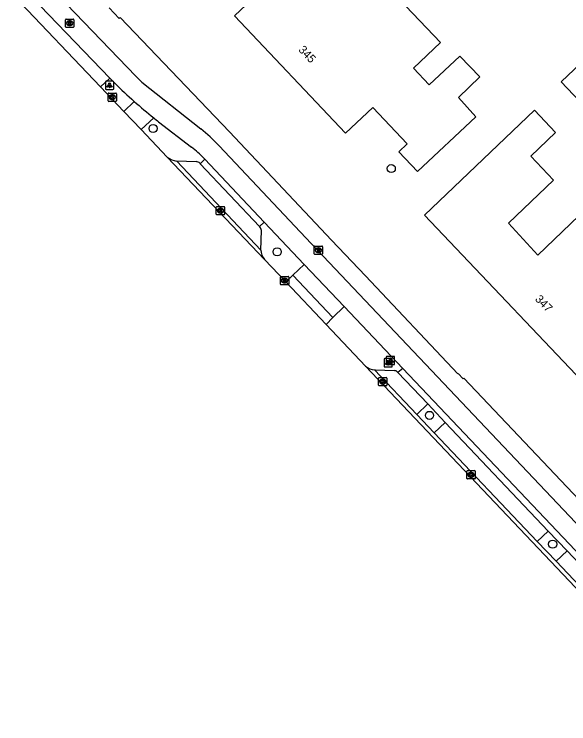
# Model space of a CAD drawing. Extents: x 162532 to 163264, y 381233 to 382042.
# Drawn here: x 163046.9 to 163113.5, y 381251.9 to 381337 of the extents above; entities that cross this region are included whole.
import ezdxf

# ---------------------------------------------------------------- set-up
doc = ezdxf.new("R2010")
doc.units = 0
for name, color, linetype in [('IMGEO_Berm_open', 7, 'Continuous'), ('IMGEO_Boom', 7, 'Continuous'), ('IMGEO_Brandkraan', 7, 'Continuous'), ('IMGEO_Fietspad_gesloten', 7, 'Continuous'), ('IMGEO_Kolk', 7, 'Continuous'), ('IMGEO_Lichtpunt', 7, 'Continuous'), ('IMGEO_Pand', 7, 'Continuous'), ('IMGEO_Pand_nummerreeks', 7, 'Continuous'), ('IMGEO_Parkeervlak_open', 7, 'Continuous'), ('IMGEO_Rijbaan_lokaal_gesloten', 7, 'Continuous'), ('IMGEO_Rijbaan_lokaal_open', 7, 'Continuous'), ('IMGEO_Rioolput', 7, 'Continuous'), ('IMGEO_Voetpad_open', 7, 'Continuous')]:
    doc.layers.add(name, color=color, linetype=linetype)

msp = doc.modelspace()

# ---------------------------------------------------------------- linework, layer by layer
at = {"layer": 'IMGEO_Berm_open'}
for points in [[(163069.769, 381319.62), (163069.229, 381319.072)], [(163076.341, 381311.55), (163076.898, 381312.067)], [(163093.518, 381294.532), (163092.951, 381294.025)], [(163096.521, 381290.265), (163098.617, 381288.057)], [(163113.256, 381272.637), (163110.99, 381275.023)]]:
    msp.add_lwpolyline(points, dxfattribs=at)
at = {"layer": 'IMGEO_Boom'}
for centre in [(163063.565, 381323.301), (163092.143, 381318.497), (163078.459, 381308.505), (163096.733, 381288.889), (163111.511, 381273.445)]:
    msp.add_circle(centre, 0.489, dxfattribs=at)
at = {"layer": 'IMGEO_Brandkraan'}
for p, q in [((163082.901, 381308.266), (163082.901, 381309.118)), ((163082.976, 381309.192), (163083.828, 381309.192)), ((163083.389, 381308.972), (163083.414, 381308.972)), ((163083.902, 381309.118), (163083.902, 381308.266)), ((163083.828, 381308.192), (163082.976, 381308.192)), ((163083.412, 381308.412), (163083.387, 381308.412))]:
    msp.add_line(p, q, dxfattribs=at)
for points in [[(163082.901, 381308.266), (163082.901, 381309.118)], [(163082.976, 381309.192), (163083.828, 381309.192)], [(163083.249, 381308.892), (163083.249, 381308.492), (163083.462, 381308.492)], [(163083.48, 381308.892), (163083.249, 381308.892)], [(163083.428, 381308.811), (163083.374, 381308.811), (163083.374, 381308.735)], [(163083.902, 381309.118), (163083.902, 381308.266)], [(163083.828, 381308.192), (163082.976, 381308.192)], [(163083.374, 381308.735), (163083.427, 381308.735)], [(163083.436, 381308.659), (163083.374, 381308.659), (163083.374, 381308.578)], [(163083.374, 381308.578), (163083.436, 381308.578)]]:
    msp.add_lwpolyline(points, dxfattribs=at)
for centre, radius, start, end in [((163082.978, 381309.116), 0.0765, 91.55205, 178.44795), ((163082.978, 381309.116), 0.0765, 91.55205, 178.44795), ((163083.429, 381308.773), 0.0379, 267.82845, 90.93552), ((163083.484, 381308.747), 0.145, 59.4692, 91.53667), ((163083.509, 381308.794), 0.0922, 285.51372, 58.15012), ((163083.826, 381309.116), 0.0765, 1.55205, 88.44795), ((163083.826, 381309.116), 0.0765, 1.55205, 88.44795), ((163082.978, 381308.268), 0.0765, 181.55205, 268.44795), ((163082.978, 381308.268), 0.0765, 181.55205, 268.44795), ((163083.437, 381308.618), 0.0404, 269.87594, 90.50774), ((163083.468, 381308.743), 0.251, 268.66757, 293.53466), ((163083.514, 381308.602), 0.105, 301.31148, 78.98903), ((163083.826, 381308.268), 0.0765, 271.55205, 358.44795), ((163083.826, 381308.268), 0.0765, 271.55205, 358.44795)]:
    msp.add_arc(centre, radius, start, end, dxfattribs=at)
for centre, major_axis, ratio, start_param, end_param in [((163083.388, 381308.692), (-0.387, 0.002), 0.722429, 4.712389, 7.853982), ((163083.413, 381308.692), (-0.39, 0.002), 0.717154, 1.570796, 4.712389)]:
    msp.add_ellipse(centre, major_axis=major_axis, ratio=ratio, start_param=start_param, end_param=end_param, dxfattribs=at)
at = {"layer": 'IMGEO_Fietspad_gesloten'}
for points in [[(163049.024, 381342.557), (163061.485, 381329.585), (163062.213, 381328.878), (163069.293, 381323.282)], [(163058.375, 381329.349), (163058.969, 381328.729)], [(163064.228, 381324.12), (163068.172, 381321.081)], [(163071.49, 381321.218), (163082.544, 381309.501), (163135.158, 381253.984), (163136.659, 381252.418)], [(163069.687, 381319.707), (163069.769, 381319.62)], [(163069.769, 381319.62), (163076.898, 381312.067)], [(163076.898, 381312.067), (163081.69, 381306.989)], [(163086.482, 381301.942), (163093.518, 381294.532)], [(163093.518, 381294.532), (163129.771, 381256.351)]]:
    msp.add_lwpolyline(points, dxfattribs=at)
for centre, radius, start, end in [((163102.92, 381373.565), 62.785, 225.57143, 228.47668), ((163102.439, 381373.008), 62.05, 228.46808, 231.30457), ((163102.873, 381373.527), 62.725, 231.29153, 231.96845), ((163055.156, 381306.033), 22.302, 42.91261, 50.66302), ((163058.539, 381308.937), 15.501, 44.01146, 51.57684)]:
    msp.add_arc(centre, radius, start, end, dxfattribs=at)
at = {"layer": 'IMGEO_Kolk'}
for p, q in [((163058.243, 381327.554), (163059.095, 381327.554)), ((163058.168, 381326.628), (163058.168, 381327.48)), ((163058.679, 381326.774), (163058.654, 381326.774)), ((163058.656, 381327.334), (163058.681, 381327.334)), ((163059.169, 381327.48), (163059.169, 381326.628)), ((163059.095, 381326.554), (163058.243, 381326.554)), ((163071.149, 381313.021), (163071.149, 381313.873)), ((163071.224, 381313.947), (163072.076, 381313.947)), ((163072.15, 381313.873), (163072.15, 381313.021)), ((163071.66, 381313.167), (163071.635, 381313.167)), ((163071.637, 381313.727), (163071.662, 381313.727)), ((163072.076, 381312.947), (163071.224, 381312.947)), ((163078.834, 381304.631), (163078.834, 381305.483)), ((163078.909, 381305.557), (163079.761, 381305.557)), ((163079.835, 381305.483), (163079.835, 381304.631)), ((163079.761, 381304.557), (163078.909, 381304.557)), ((163079.345, 381304.777), (163079.32, 381304.777)), ((163079.322, 381305.337), (163079.347, 381305.337)), ((163090.625, 381292.511), (163090.625, 381293.363)), ((163090.7, 381293.437), (163091.552, 381293.437)), ((163091.136, 381292.657), (163091.111, 381292.657)), ((163091.113, 381293.217), (163091.138, 381293.217)), ((163091.626, 381293.363), (163091.626, 381292.511)), ((163091.552, 381292.437), (163090.7, 381292.437)), ((163101.215, 381281.337), (163101.215, 381282.189)), ((163101.29, 381282.263), (163102.142, 381282.263)), ((163101.703, 381282.043), (163101.728, 381282.043)), ((163102.216, 381282.189), (163102.216, 381281.337)), ((163102.142, 381281.263), (163101.29, 381281.263)), ((163101.726, 381281.483), (163101.701, 381281.483))]:
    msp.add_line(p, q, dxfattribs=at)
for points in [[(163058.243, 381327.554), (163059.095, 381327.554)], [(163058.168, 381326.628), (163058.168, 381327.48)], [(163058.489, 381327.254), (163058.612, 381327.254), (163058.612, 381327.103), (163058.742, 381327.254), (163058.906, 381327.254), (163058.76, 381327.103), (163058.913, 381326.854), (163058.761, 381326.854), (163058.676, 381327.018), (163058.612, 381326.951), (163058.612, 381326.854), (163058.489, 381326.854), (163058.489, 381327.254)], [(163059.169, 381327.48), (163059.169, 381326.628)], [(163059.095, 381326.554), (163058.243, 381326.554)], [(163071.149, 381313.021), (163071.149, 381313.873)], [(163071.224, 381313.947), (163072.076, 381313.947)], [(163072.15, 381313.873), (163072.15, 381313.021)], [(163071.47, 381313.647), (163071.593, 381313.647), (163071.593, 381313.496), (163071.723, 381313.647), (163071.887, 381313.647), (163071.741, 381313.496), (163071.894, 381313.247), (163071.742, 381313.247), (163071.657, 381313.411), (163071.593, 381313.344), (163071.593, 381313.247), (163071.47, 381313.247), (163071.47, 381313.647)], [(163072.076, 381312.947), (163071.224, 381312.947)], [(163078.834, 381304.631), (163078.834, 381305.483)], [(163078.909, 381305.557), (163079.761, 381305.557)], [(163079.835, 381305.483), (163079.835, 381304.631)], [(163079.761, 381304.557), (163078.909, 381304.557)], [(163079.155, 381305.257), (163079.278, 381305.257), (163079.278, 381305.106), (163079.408, 381305.257), (163079.572, 381305.257), (163079.426, 381305.106), (163079.579, 381304.857), (163079.427, 381304.857), (163079.342, 381305.021), (163079.278, 381304.954), (163079.278, 381304.857), (163079.155, 381304.857), (163079.155, 381305.257)], [(163090.625, 381292.511), (163090.625, 381293.363)], [(163090.7, 381293.437), (163091.552, 381293.437)], [(163090.946, 381293.137), (163091.069, 381293.137), (163091.069, 381292.986), (163091.199, 381293.137), (163091.363, 381293.137), (163091.217, 381292.986), (163091.37, 381292.737), (163091.218, 381292.737), (163091.133, 381292.901), (163091.069, 381292.834), (163091.069, 381292.737), (163090.946, 381292.737), (163090.946, 381293.137)], [(163091.626, 381293.363), (163091.626, 381292.511)], [(163091.552, 381292.437), (163090.7, 381292.437)], [(163101.215, 381281.337), (163101.215, 381282.189)], [(163101.29, 381282.263), (163102.142, 381282.263)], [(163101.536, 381281.963), (163101.659, 381281.963), (163101.659, 381281.812), (163101.789, 381281.963), (163101.953, 381281.963), (163101.807, 381281.812), (163101.96, 381281.563), (163101.808, 381281.563), (163101.723, 381281.727), (163101.659, 381281.66), (163101.659, 381281.563), (163101.536, 381281.563), (163101.536, 381281.963)], [(163102.216, 381282.189), (163102.216, 381281.337)], [(163102.142, 381281.263), (163101.29, 381281.263)]]:
    msp.add_lwpolyline(points, dxfattribs=at)
for centre, start, end in [((163058.245, 381327.478), 91.55205, 178.44795), ((163058.245, 381327.478), 91.55205, 178.44795), ((163059.093, 381327.478), 1.55205, 88.44795), ((163059.093, 381327.478), 1.55205, 88.44795), ((163058.245, 381326.63), 181.55205, 268.44795), ((163058.245, 381326.63), 181.55205, 268.44795), ((163059.093, 381326.63), 271.55205, 358.44795), ((163059.093, 381326.63), 271.55205, 358.44795), ((163071.226, 381313.871), 91.55205, 178.44795), ((163071.226, 381313.871), 91.55205, 178.44795), ((163072.074, 381313.871), 1.55205, 88.44795), ((163072.074, 381313.871), 1.55205, 88.44795), ((163071.226, 381313.023), 181.55205, 268.44795), ((163071.226, 381313.023), 181.55205, 268.44795), ((163072.074, 381313.023), 271.55205, 358.44795), ((163072.074, 381313.023), 271.55205, 358.44795), ((163078.911, 381305.481), 91.55205, 178.44795), ((163078.911, 381305.481), 91.55205, 178.44795), ((163079.759, 381305.481), 1.55205, 88.44795), ((163079.759, 381305.481), 1.55205, 88.44795), ((163078.911, 381304.633), 181.55205, 268.44795), ((163078.911, 381304.633), 181.55205, 268.44795), ((163079.759, 381304.633), 271.55205, 358.44795), ((163079.759, 381304.633), 271.55205, 358.44795), ((163090.702, 381293.361), 91.55205, 178.44795), ((163090.702, 381293.361), 91.55205, 178.44795), ((163091.55, 381293.361), 1.55205, 88.44795), ((163091.55, 381293.361), 1.55205, 88.44795), ((163090.702, 381292.513), 181.55205, 268.44795), ((163090.702, 381292.513), 181.55205, 268.44795), ((163091.55, 381292.513), 271.55205, 358.44795), ((163091.55, 381292.513), 271.55205, 358.44795), ((163101.292, 381282.187), 91.55205, 178.44795), ((163101.292, 381282.187), 91.55205, 178.44795), ((163102.14, 381282.187), 1.55205, 88.44795), ((163102.14, 381282.187), 1.55205, 88.44795), ((163101.292, 381281.339), 181.55205, 268.44795), ((163101.292, 381281.339), 181.55205, 268.44795), ((163102.14, 381281.339), 271.55205, 358.44795), ((163102.14, 381281.339), 271.55205, 358.44795)]:
    msp.add_arc(centre, 0.0765, start, end, dxfattribs=at)
for centre, major_axis, ratio, start_param, end_param in [((163058.655, 381327.054), (-0.387, 0.002), 0.722429, 4.712389, 7.853982), ((163058.68, 381327.054), (-0.39, 0.002), 0.717154, 1.570796, 4.712389), ((163071.636, 381313.447), (-0.387, 0.002), 0.722429, 4.712389, 7.853982), ((163071.661, 381313.447), (-0.39, 0.002), 0.717154, 1.570796, 4.712389), ((163079.321, 381305.057), (-0.387, 0.002), 0.722429, 4.712389, 7.853982), ((163079.346, 381305.057), (-0.39, 0.002), 0.717154, 1.570796, 4.712389), ((163091.112, 381292.937), (-0.387, 0.002), 0.722429, 4.712389, 7.853982), ((163091.137, 381292.937), (-0.39, 0.002), 0.717154, 1.570796, 4.712389), ((163101.702, 381281.763), (-0.387, 0.002), 0.722429, 4.712389, 7.853982), ((163101.727, 381281.763), (-0.39, 0.002), 0.717154, 1.570796, 4.712389)]:
    msp.add_ellipse(centre, major_axis=major_axis, ratio=ratio, start_param=start_param, end_param=end_param, dxfattribs=at)
at = {"layer": 'IMGEO_Lichtpunt'}
for p, q in [((163057.841, 381328.877), (163057.841, 381328.07)), ((163057.841, 381328.877), (163057.841, 381328.07)), ((163058.743, 381328.972), (163057.935, 381328.972)), ((163058.743, 381328.972), (163057.935, 381328.972)), ((163058.837, 381328.07), (163058.837, 381328.877)), ((163058.837, 381328.07), (163058.837, 381328.877)), ((163057.935, 381327.976), (163058.743, 381327.976)), ((163057.935, 381327.976), (163058.743, 381327.976)), ((163091.276, 381295.609), (163091.276, 381294.802)), ((163091.276, 381295.609), (163091.276, 381294.802)), ((163092.178, 381295.704), (163091.37, 381295.704)), ((163092.178, 381295.704), (163091.37, 381295.704)), ((163091.55, 381295.879), (163091.55, 381295.072)), ((163091.55, 381295.879), (163091.55, 381295.072)), ((163092.452, 381295.974), (163091.644, 381295.974)), ((163092.452, 381295.974), (163091.644, 381295.974)), ((163092.272, 381294.802), (163092.272, 381295.609)), ((163092.272, 381294.802), (163092.272, 381295.609)), ((163092.546, 381295.072), (163092.546, 381295.879)), ((163092.546, 381295.072), (163092.546, 381295.879)), ((163091.37, 381294.708), (163092.178, 381294.708)), ((163091.37, 381294.708), (163092.178, 381294.708)), ((163091.644, 381294.978), (163092.452, 381294.978)), ((163091.644, 381294.978), (163092.452, 381294.978))]:
    msp.add_line(p, q, dxfattribs=at)
for points in [[(163058.215, 381328.541), (163058.254, 381328.513), (163058.066, 381328.251), (163058.028, 381328.278), (163058.215, 381328.541)], [(163058.317, 381328.493), (163058.364, 381328.493), (163058.364, 381328.171), (163058.317, 381328.171), (163058.317, 381328.493)], [(163058.427, 381328.513), (163058.465, 381328.54), (163058.652, 381328.278), (163058.613, 381328.25), (163058.427, 381328.513)], [(163091.65, 381295.273), (163091.689, 381295.245), (163091.501, 381294.983), (163091.463, 381295.01), (163091.65, 381295.273)], [(163091.924, 381295.543), (163091.963, 381295.515), (163091.775, 381295.253), (163091.737, 381295.28), (163091.924, 381295.543)], [(163091.752, 381295.225), (163091.799, 381295.225), (163091.799, 381294.903), (163091.752, 381294.903), (163091.752, 381295.225)], [(163091.862, 381295.245), (163091.9, 381295.272), (163092.087, 381295.01), (163092.048, 381294.982), (163091.862, 381295.245)], [(163092.026, 381295.495), (163092.073, 381295.495), (163092.073, 381295.173), (163092.026, 381295.173), (163092.026, 381295.495)], [(163092.136, 381295.515), (163092.174, 381295.542), (163092.361, 381295.28), (163092.322, 381295.252), (163092.136, 381295.515)]]:
    msp.add_lwpolyline(points, dxfattribs=at)
for centre in [(163058.34, 381328.675), (163091.775, 381295.407), (163092.049, 381295.677)]:
    msp.add_circle(centre, 0.0994, dxfattribs=at)
for centre, start, end in [((163057.935, 381328.877), 90, 180), ((163057.935, 381328.877), 90, 180), ((163058.743, 381328.877), 0, 90), ((163058.743, 381328.877), 0, 90), ((163057.935, 381328.07), 180, 270), ((163057.935, 381328.07), 180, 270), ((163058.743, 381328.07), 270, 0), ((163058.743, 381328.07), 270, 360), ((163091.37, 381295.609), 90, 180), ((163091.37, 381295.609), 90, 180), ((163091.644, 381295.879), 90, 180), ((163091.644, 381295.879), 90, 180), ((163092.178, 381295.609), 0, 90), ((163092.178, 381295.609), 0, 90), ((163092.452, 381295.879), 0, 90), ((163092.452, 381295.879), 0, 90), ((163091.37, 381294.802), 180, 270), ((163091.37, 381294.802), 180, 270), ((163091.644, 381295.072), 180, 270), ((163091.644, 381295.072), 180, 270), ((163092.178, 381294.802), 270, 0), ((163092.178, 381294.802), 270, 360), ((163092.452, 381295.072), 270, 0), ((163092.452, 381295.072), 270, 360)]:
    msp.add_arc(centre, 0.0946, start, end, dxfattribs=at)
at = {"layer": 'IMGEO_Pand'}
for points in [[(163085.503, 381346.81), (163098.042, 381333.625), (163094.795, 381330.537), (163096.711, 381328.523), (163100.361, 381331.979), (163102.759, 381329.485), (163100.214, 381327.039), (163102.29, 381324.687), (163095.283, 381318.144), (163093.064, 381320.497), (163094.058, 381321.48), (163089.938, 381325.841), (163086.673, 381322.745), (163073.337, 381336.809), (163077.494, 381340.759)], [(163118.101, 381289.79), (163096.134, 381312.906), (163109.324, 381325.485), (163111.856, 381322.816), (163108.885, 381319.993), (163111.626, 381317.107), (163106.201, 381311.953), (163109.72, 381308.122), (163121.53, 381319.421), (163112.53, 381328.913), (163118.755, 381334.82)]]:
    msp.add_lwpolyline(points, dxfattribs=at)
at = {"layer": 'IMGEO_Parkeervlak_open'}
for points in [[(163076.508, 381308.729), (163066.399, 381319.385)], [(163068.75, 381319.325), (163066.399, 381319.385)], [(163069.229, 381319.072), (163069.17, 381319.135)], [(163069.229, 381319.072), (163076.341, 381311.55)], [(163076.391, 381311.497), (163076.341, 381311.55)], [(163076.508, 381308.729), (163076.568, 381311.056)], [(163095.2, 381289.018), (163090.135, 381294.355)], [(163090.273, 381294.35), (163092.497, 381294.26)], [(163092.901, 381294.078), (163092.951, 381294.025)], [(163092.951, 381294.025), (163096.521, 381290.265)], [(163095.2, 381289.018), (163096.521, 381290.265)], [(163097.29, 381286.809), (163095.2, 381289.018)], [(163098.617, 381288.057), (163097.29, 381286.809)], [(163098.617, 381288.057), (163110.99, 381275.023)], [(163109.657, 381273.747), (163097.29, 381286.809)], [(163110.99, 381275.023), (163109.657, 381273.747)], [(163109.657, 381273.747), (163111.948, 381271.386)], [(163111.948, 381271.386), (163113.256, 381272.637)], [(163113.256, 381272.637), (163129.217, 381255.823)], [(163129.384, 381252.989), (163111.948, 381271.386)]]:
    msp.add_lwpolyline(points, dxfattribs=at)
for centre, radius, start, end in [((163066.741, 381321.796), 2.435, 232.46675, 261.93773), ((163068.68, 381318.611), 0.718, 46.92736, 84.39046), ((163075.739, 381310.979), 0.832, 5.28073, 38.45642), ((163078.321, 381308.762), 1.813, 181.05275, 220.4978), ((163090.269, 381296.178), 1.828, 228.21467, 265.79703), ((163090.262, 381295.941), 1.591, 265.43751, 270.41244), ((163092.522, 381293.775), 0.485, 38.59088, 92.90646)]:
    msp.add_arc(centre, radius, start, end, dxfattribs=at)
at = {"layer": 'IMGEO_Rijbaan_lokaal_gesloten'}
for points in [[(163057.246, 381328.286), (163046.897, 381339.212)], [(163060.051, 381325.338), (163057.246, 381328.286)], [(163062.115, 381323.168), (163060.051, 381325.338)], [(163065.257, 381319.865), (163062.115, 381323.168)], [(163076.942, 381307.585), (163065.257, 381319.865)], [(163079.482, 381304.902), (163076.942, 381307.585)], [(163084.32, 381299.797), (163079.482, 381304.902)], [(163089.051, 381294.815), (163084.32, 381299.797)], [(163129.773, 381251.897), (163089.051, 381294.815)]]:
    msp.add_lwpolyline(points, dxfattribs=at)
at = {"layer": 'IMGEO_Rijbaan_lokaal_open'}
for points in [[(163047.948, 381340.2), (163058.375, 381329.349)], [(163057.246, 381328.286), (163058.375, 381329.349)], [(163081.69, 381306.989), (163080.328, 381305.702)], [(163081.69, 381306.989), (163086.482, 381301.942)], [(163080.328, 381305.702), (163079.482, 381304.902)], [(163085.143, 381300.614), (163080.328, 381305.702)], [(163086.482, 381301.942), (163085.143, 381300.614)], [(163085.143, 381300.614), (163084.32, 381299.797)]]:
    msp.add_lwpolyline(points, dxfattribs=at)
at = {"layer": 'IMGEO_Rioolput'}
for p, q in [((163053.055, 381335.503), (163053.055, 381336.355)), ((163053.13, 381336.429), (163053.982, 381336.429)), ((163053.543, 381336.209), (163053.568, 381336.209)), ((163054.056, 381336.355), (163054.056, 381335.503)), ((163053.982, 381335.429), (163053.13, 381335.429)), ((163053.566, 381335.649), (163053.541, 381335.649))]:
    msp.add_line(p, q, dxfattribs=at)
for points in [[(163053.055, 381335.503), (163053.055, 381336.355)], [(163053.13, 381336.429), (163053.982, 381336.429)], [(163053.644, 381336.127), (163053.392, 381336.129), (163053.392, 381335.729)], [(163053.57, 381336.048), (163053.516, 381336.048), (163053.516, 381335.967)], [(163054.056, 381336.355), (163054.056, 381335.503)], [(163053.982, 381335.429), (163053.13, 381335.429)], [(163053.392, 381335.729), (163053.516, 381335.729), (163053.516, 381335.891), (163053.527, 381335.891)], [(163053.516, 381335.967), (163053.568, 381335.967)], [(163053.574, 381335.862), (163053.645, 381335.729), (163053.785, 381335.729), (163053.72, 381335.855)]]:
    msp.add_lwpolyline(points, dxfattribs=at)
for centre, radius, start, end in [((163053.132, 381336.353), 0.0765, 91.55205, 178.44795), ((163053.132, 381336.353), 0.0765, 91.55205, 178.44795), ((163053.576, 381335.952), 0.0964, 77.00612, 93.18647), ((163053.59, 381336.009), 0.0378, 276.66336, 79.67722), ((163053.643, 381336.017), 0.109, 350.36119, 89.41601), ((163053.98, 381336.353), 0.0765, 1.55205, 88.44795), ((163053.98, 381336.353), 0.0765, 1.55205, 88.44795), ((163053.132, 381335.505), 0.0765, 181.55205, 268.44795), ((163053.132, 381335.505), 0.0765, 181.55205, 268.44795), ((163053.526, 381335.838), 0.0533, 26.02933, 88.69889), ((163053.552, 381336.156), 0.19, 274.7715, 282.96867), ((163053.641, 381336.017), 0.112, 277.58423, 350.98172), ((163053.625, 381335.802), 0.108, 29.51342, 73.79051), ((163053.98, 381335.505), 0.0765, 271.55205, 358.44795), ((163053.98, 381335.505), 0.0765, 271.55205, 358.44795)]:
    msp.add_arc(centre, radius, start, end, dxfattribs=at)
for centre, major_axis, ratio, start_param, end_param in [((163053.542, 381335.929), (-0.387, 0.002), 0.722429, 4.712389, 7.853982), ((163053.567, 381335.929), (-0.39, 0.002), 0.717154, 1.570796, 4.712389)]:
    msp.add_ellipse(centre, major_axis=major_axis, ratio=ratio, start_param=start_param, end_param=end_param, dxfattribs=at)
at = {"layer": 'IMGEO_Voetpad_open'}
for points in [[(163152.909, 381270.379), (163128.532, 381264.15), (163100.872, 381293.349), (163100.793, 381293.273), (163100.168, 381293.933), (163100.121, 381293.889), (163089.036, 381305.65), (163084.973, 381309.929), (163072.718, 381322.884), (163059.601, 381336.637), (163059.475, 381336.516), (163058.294, 381337.784)], [(163061.298, 381326.559), (163060.051, 381325.338)], [(163062.115, 381323.168), (163063.647, 381324.58)]]:
    msp.add_lwpolyline(points, dxfattribs=at)

# ---------------------------------------------------------------- texts
at = {"layer": 'IMGEO_Pand_nummerreeks'}
for s, rotation, p in [('345', 313.64277, (163080.939, 381332.683)), ('347', 313.79919, (163109.328, 381302.776))]:
    msp.add_text(s, height=1, rotation=rotation, dxfattribs=at).set_placement(p)

doc.saveas('drawing.dxf')
